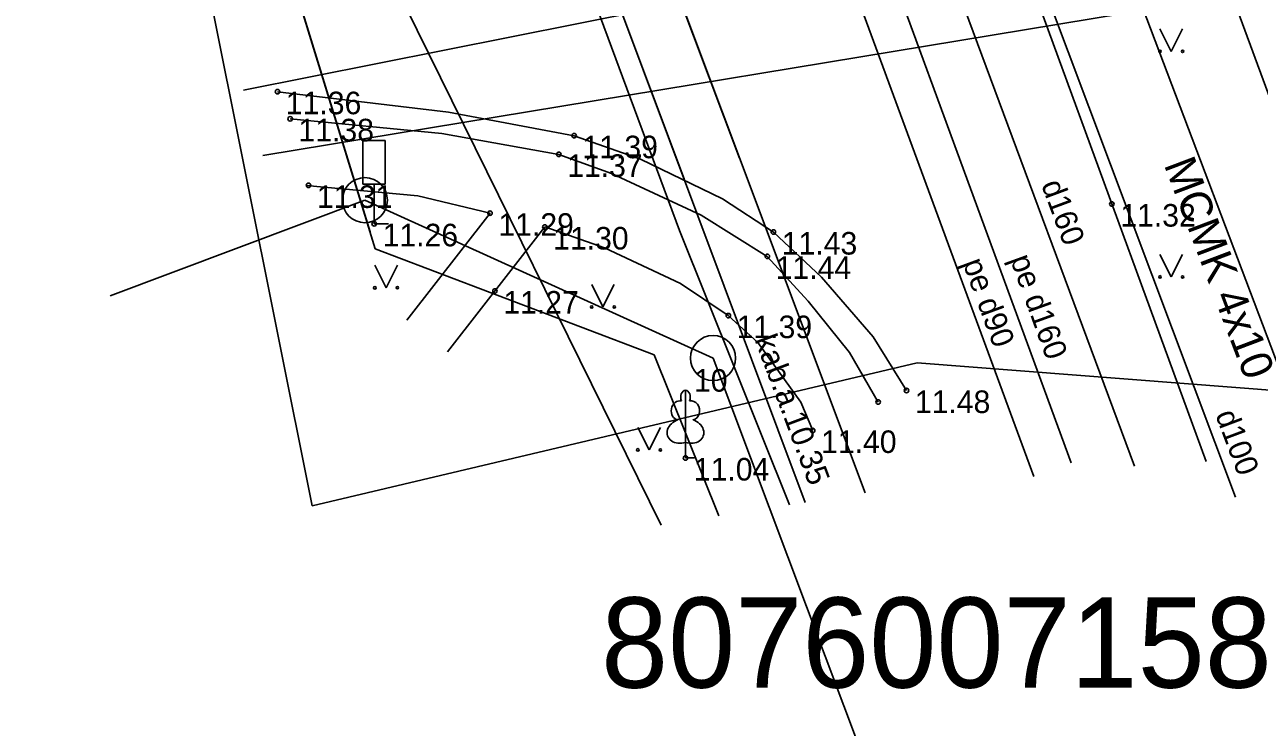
# Model space of a CAD drawing. Extents: x 503353 to 504004, y 304662 to 305049.
# Drawn here: x 503377.08 to 503404.45, y 304952.51 to 304968.09 of the extents above; entities that cross this region are included whole.
import ezdxf

# ---------------------------------------------------------------- set-up
doc = ezdxf.new("R2010")
doc.units = 0
for name, color, linetype in [('59', 7, 'Continuous'), ('APGR_ELEM_####_####_#', 7, 'Continuous'), ('APGR_SARK_####_####_#', 7, 'Continuous'), ('APGS_VADP_ZSPR_####_#', 7, 'Continuous'), ('APGS_VADP_ZSPR_TKST_#', 7, 'Continuous'), ('CELI_CMAL_####_####_#', 7, 'Continuous'), ('CELI_ELEM_####_####_#', 7, 'Continuous'), ('ELEK_ACRL_####_####_#', 7, 'Continuous'), ('ELEK_VADP_VSPR_####_#', 7, 'Continuous'), ('ELEK_VADP_ZSPR_####_#', 7, 'Continuous'), ('ELEK_VADP_ZSPR_TKST_#', 7, 'Continuous'), ('GAZE_VADP_VSP1_####_#', 7, 'Continuous'), ('GAZE_VADP_VSP1_TKST_#', 7, 'Continuous'), ('GAZE_VADP_VSP2_####_#', 7, 'Continuous'), ('GAZE_VADP_VSP2_TKST_#', 7, 'Continuous'), ('HIDG_PLIN_####_####_#', 7, 'Continuous'), ('LKAN_VADP_PAST_####_#', 7, 'Continuous'), ('RAMI_UZMR_####_####_#', 7, 'Continuous'), ('RELJ_AATZ_####_TKST_#', 7, 'Continuous'), ('RELJ_ELEM_####_####_#', 7, 'Continuous'), ('RELJ_NOGA_####_####_#', 7, 'Continuous'), ('SAKK_KKAN_####_####_#', 7, 'Continuous'), ('SKAN_VADP_PAST_####_#', 7, 'Continuous'), ('SKAN_VADP_SPDK_####_#', 7, 'Continuous'), ('SKAN_VADP_SPDK_TKST_#', 7, 'Continuous'), ('TERT_DIAM_####_TKST_#', 7, 'Continuous'), ('TERT_ELEM_####_####_#', 7, 'Continuous'), ('UDTK_VADP_UDEN_####_#', 7, 'Continuous'), ('UDTK_VADP_UDEN_TKST_#', 7, 'Continuous')]:
    doc.layers.add(name, color=color, linetype=linetype)

msp = doc.modelspace()

# ---------------------------------------------------------------- linework, layer by layer
at = {"layer": 'APGR_ELEM_####_####_#'}
for centre in [(503384.62, 304964.2), (503392.34, 304960.7)]:
    msp.add_circle(centre, 0.5, dxfattribs=at)
at = {"layer": 'APGR_SARK_####_####_#'}
for p, q in [((503378.972, 304962.083), (503384.617, 304964.203)), ((503392.344, 304960.696), (503384.617, 304964.203)), ((503392.344, 304960.696), (503396.992, 304948.32))]:
    msp.add_line(p, q, dxfattribs=at)
at = {"layer": 'APGS_VADP_ZSPR_####_#'}
msp.add_line((503405.972, 304957.61), (503401.476, 304969.504), dxfattribs=at)
at = {"layer": 'CELI_CMAL_####_####_#'}
for points in [[(503393.097, 304986.219), (503403.273, 304958.405)], [(503382.681, 304966.606), (503386.472, 304966.152), (503389.259, 304965.631), (503390.729, 304965.109), (503392.551, 304964.228), (503393.678, 304963.495), (503394.748, 304962.497), (503395.892, 304961.168), (503396.629, 304959.982)], [(503396.002, 304959.725), (503395.367, 304960.827), (503394.449, 304961.965), (503393.543, 304962.955), (503392.073, 304963.872), (503390.087, 304964.789), (503388.92, 304965.217), (503386.328, 304965.679), (503382.962, 304966.005)], [(503383.32, 304964.529), (503385.792, 304964.294), (503387.395, 304963.912)], [(503385.55, 304961.541), (503387.395, 304963.912)], [(503386.453, 304960.837), (503388.609, 304963.607)], [(503388.609, 304963.607), (503389.935, 304963.148), (503391.617, 304962.354), (503392.677, 304961.642), (503393.336, 304961.044), (503394.285, 304959.724), (503394.55, 304959.096)]]:
    msp.add_lwpolyline(points, dxfattribs=at)
at = {"layer": 'CELI_ELEM_####_####_#'}
for p, q in [((503385.073, 304965.525), (503384.573, 304965.525)), ((503384.573, 304964.556), (503384.573, 304965.525)), ((503385.073, 304964.556), (503385.073, 304965.525)), ((503385.073, 304964.556), (503384.573, 304964.556)), ((503384.827, 304964.556), (503384.827, 304963.678)), ((503384.827, 304963.678), (503385.142, 304963.678))]:
    msp.add_line(p, q, dxfattribs=at)
at = {"layer": 'ELEK_ACRL_####_####_#'}
for p, q in [((503386.601, 304981.987), (503392.927, 304965.13)), ((503385.387, 304981.535), (503391.699, 304964.676))]:
    msp.add_line(p, q, dxfattribs=at)
msp.add_lwpolyline([(503384.736, 304963.501), (503380.029, 304978.827)], dxfattribs=at)
at = {"layer": 'ELEK_VADP_VSPR_####_#'}
for p, q in [((503386.023, 304978.574), (503391.594, 304963.529)), ((503391.594, 304963.529), (503394.032, 304957.446))]:
    msp.add_line(p, q, dxfattribs=at)
at = {"layer": 'ELEK_VADP_ZSPR_####_#'}
for p, q in [((503384.845, 304963.125), (503378.119, 304985.052)), ((503384.367, 304984.261), (503394.385, 304957.501)), ((503387.77, 304962.012), (503384.845, 304963.125))]:
    msp.add_line(p, q, dxfattribs=at)
for points in [[(503379.852, 305000), (503395.709, 304957.709)], [(503387.77, 304962.012), (503391.033, 304960.771), (503392.467, 304957.2)]]:
    msp.add_lwpolyline(points, dxfattribs=at)
at = {"layer": 'GAZE_VADP_VSP1_####_#'}
msp.add_line((503393.697, 304973.697), (503399.453, 304958.074), dxfattribs=at)
at = {"layer": 'GAZE_VADP_VSP2_####_#'}
msp.add_line((503400.28, 304958.379), (503394.546, 304974.002), dxfattribs=at)
at = {"layer": 'HIDG_PLIN_####_####_#'}
for points in [[(503419.587, 304952.537), (503416.755, 304959.536), (503412.876, 304969.575), (503409.221, 304979.701), (503405.654, 304989.86), (503402.036, 305000), (503392.74, 305025.488)], [(503411.469, 304955.877), (503406.678, 304968.605), (503404.887, 304973.537), (503403.172, 304978.498), (503401.476, 304983.466), (503399.743, 304988.42), (503397.13, 304995.726), (503394.508, 305003.029), (503389.116, 305017.581), (503386.254, 305025.055)]]:
    msp.add_spline(points, degree=3, dxfattribs=at)
at = {"layer": 'LKAN_VADP_PAST_####_#'}
msp.add_line((503381.928, 304966.643), (503403.938, 304971.025), dxfattribs=at)
at = {"layer": 'RAMI_UZMR_####_####_#'}
msp.add_lwpolyline([(503407.219, 305023.925), (503368.776, 305020.183), (503379.431, 304977.462), (503383.452, 304957.421), (503396.867, 304960.598), (503416.959, 304959.032), (503433.698, 304951.36), (503608.791, 304871.751), (503642.724, 304858.177), (503694.651, 304834.724), (503842.283, 304765.867)], dxfattribs=at)
at = {"layer": 'RELJ_ELEM_####_####_#'}
for centre in [(503382.681, 304966.606), (503382.962, 304966.005), (503389.259, 304965.631), (503388.92, 304965.217), (503383.37, 304964.529), (503401.184, 304964.115), (503387.395, 304963.912), (503384.827, 304963.678), (503388.609, 304963.607), (503393.678, 304963.495), (503393.543, 304962.955), (503387.503, 304962.186), (503392.677, 304961.642), (503396.629, 304959.982), (503396.002, 304959.725), (503394.55, 304959.096), (503391.728, 304958.485)]:
    msp.add_circle(centre, 0.05, dxfattribs=at)
at = {"layer": 'RELJ_NOGA_####_####_#'}
for points in [[(503421.793, 304953.375), (503418.978, 304960.8), (503411.664, 304980.395), (503404.379, 305000), (503394.998, 305025.189)], [(503421.793, 304953.375), (503418.978, 304960.8), (503411.664, 304980.395), (503404.379, 305000), (503395.14, 305024.807)], [(503410.247, 304955.404), (503401.902, 304976.94), (503397.494, 304988.727), (503387.268, 305016.834), (503384.58, 305024.465)]]:
    msp.add_spline(points, degree=3, dxfattribs=at)
at = {"layer": 'SAKK_KKAN_####_####_#'}
msp.add_line((503382.355, 304965.193), (503403.85, 304968.741), dxfattribs=at)
msp.add_lwpolyline([(503392.141, 305000), (503403.85, 304968.741), (503409.025, 304954.715)], dxfattribs=at)
at = {"layer": 'SKAN_VADP_PAST_####_#'}
msp.add_line((503385.519, 304968.497), (503391.188, 304956.999), dxfattribs=at)
at = {"layer": 'SKAN_VADP_SPDK_####_#'}
msp.add_line((503396.919, 304976.27), (503403.923, 304957.613), dxfattribs=at)
at = {"layer": 'TERT_ELEM_####_####_#'}
for p, q in [((503402.25, 304968), (503402.5, 304967.5)), ((503402.5, 304967.5), (503402.75, 304968)), ((503384.841, 304962.758), (503385.091, 304962.258)), ((503385.091, 304962.258), (503385.341, 304962.758)), ((503402.25, 304963), (503402.5, 304962.5)), ((503402.5, 304962.5), (503402.75, 304963)), ((503389.649, 304962.334), (503389.899, 304961.834)), ((503389.899, 304961.834), (503390.149, 304962.334)), ((503390.671, 304959.164), (503390.921, 304958.664)), ((503390.921, 304958.664), (503391.171, 304959.164)), ((503391.728, 304958.832), (503391.728, 304958.485)), ((503391.728, 304958.485), (503391.928, 304958.485))]:
    msp.add_line(p, q, dxfattribs=at)
for points in [[(503391.728, 304959.985), (503391.728, 304958.832)], [(503391.818, 304959.753), (503391.817, 304959.754)]]:
    msp.add_lwpolyline(points, dxfattribs=at)
for centre, radius in [((503402.25, 304967.5), 0.028), ((503402.75, 304967.5), 0.0263), ((503402.25, 304962.5), 0.028), ((503402.75, 304962.5), 0.0263), ((503384.841, 304962.258), 0.028), ((503385.341, 304962.258), 0.0263), ((503389.649, 304961.833), 0.028), ((503390.149, 304961.833), 0.0263), ((503390.671, 304958.664), 0.028), ((503391.171, 304958.664), 0.0263)]:
    msp.add_circle(centre, radius, dxfattribs=at)
for centre, major_axis, ratio, start_param, end_param in [((503391.6, 304959.54), (-0.039, -0.212), 0.861323, 3.141593, 6.283185), ((503391.728, 304959.835), (0, -0.15), 0.707107, 3.14537, 5.287485), ((503391.728, 304959.835), (0, -0.15), 0.707107, 0.995701, 3.137816), ((503391.856, 304959.54), (0.039, -0.212), 0.861323, 0, 3.141593), ((503391.638, 304959.078), (0.307, 0.095), 0.814445, 1.570796, 4.752015), ((503391.818, 304959.078), (-0.307, 0.095), 0.814445, 1.531171, 4.712389)]:
    msp.add_ellipse(centre, major_axis=major_axis, ratio=ratio, start_param=start_param, end_param=end_param, dxfattribs=at)
at = {"layer": 'UDTK_VADP_UDEN_####_#'}
msp.add_line((503396.075, 304973.418), (503401.683, 304958.302), dxfattribs=at)

# ---------------------------------------------------------------- texts
at = {"layer": '59'}
msp.add_text('80760071585', height=2, dxfattribs=at).set_placement((503389.856, 304953.393))
at = {"layer": 'APGS_VADP_ZSPR_TKST_#'}
msp.add_text('MCMK 4x10', height=0.7, rotation=290.7078, dxfattribs=at).set_placement((503402.331, 304964.992))
at = {"layer": 'ELEK_VADP_ZSPR_TKST_#'}
msp.add_text('kab.a.10.35', height=0.5, rotation=290.5245, dxfattribs=at).set_placement((503393.254, 304961.113))
at = {"layer": 'GAZE_VADP_VSP1_TKST_#'}
msp.add_text('pe d90', height=0.5, rotation=290.2253, dxfattribs=at).set_placement((503397.867, 304962.813))
at = {"layer": 'GAZE_VADP_VSP2_TKST_#'}
msp.add_text('pe d160', height=0.5, rotation=289.9316, dxfattribs=at).set_placement((503398.92, 304962.898))
at = {"layer": 'RELJ_AATZ_####_TKST_#'}
for s, p in [(' 11.36', (503382.681, 304966.106)), (' 11.38', (503382.962, 304965.505)), (' 11.39', (503389.259, 304965.131)), (' 11.37', (503388.92, 304964.717)), (' 11.31', (503383.37, 304964.029)), (' 11.29', (503387.395, 304963.412)), (' 11.32', (503401.184, 304963.615)), (' 11.26', (503384.827, 304963.178)), (' 11.30', (503388.609, 304963.107)), (' 11.43', (503393.678, 304962.995)), (' 11.44', (503393.543, 304962.455)), (' 11.27', (503387.503, 304961.686)), (' 11.39', (503392.677, 304961.142)), (' 11.48', (503396.629, 304959.482)), (' 11.40', (503394.55, 304958.596)), (' 11.04', (503391.728, 304957.985))]:
    msp.add_text(s, height=0.5, dxfattribs=at).set_placement(p)
at = {"layer": 'SKAN_VADP_SPDK_TKST_#'}
msp.add_text('d100', height=0.5, rotation=290.5756, dxfattribs=at).set_placement((503403.471, 304959.447))
at = {"layer": 'TERT_DIAM_####_TKST_#'}
msp.add_text('10', height=0.5, dxfattribs=at).set_placement((503391.917, 304959.955))
at = {"layer": 'UDTK_VADP_UDEN_TKST_#'}
msp.add_text('d160', height=0.5, rotation=290.423, dxfattribs=at).set_placement((503399.611, 304964.548))

doc.saveas('drawing.dxf')
